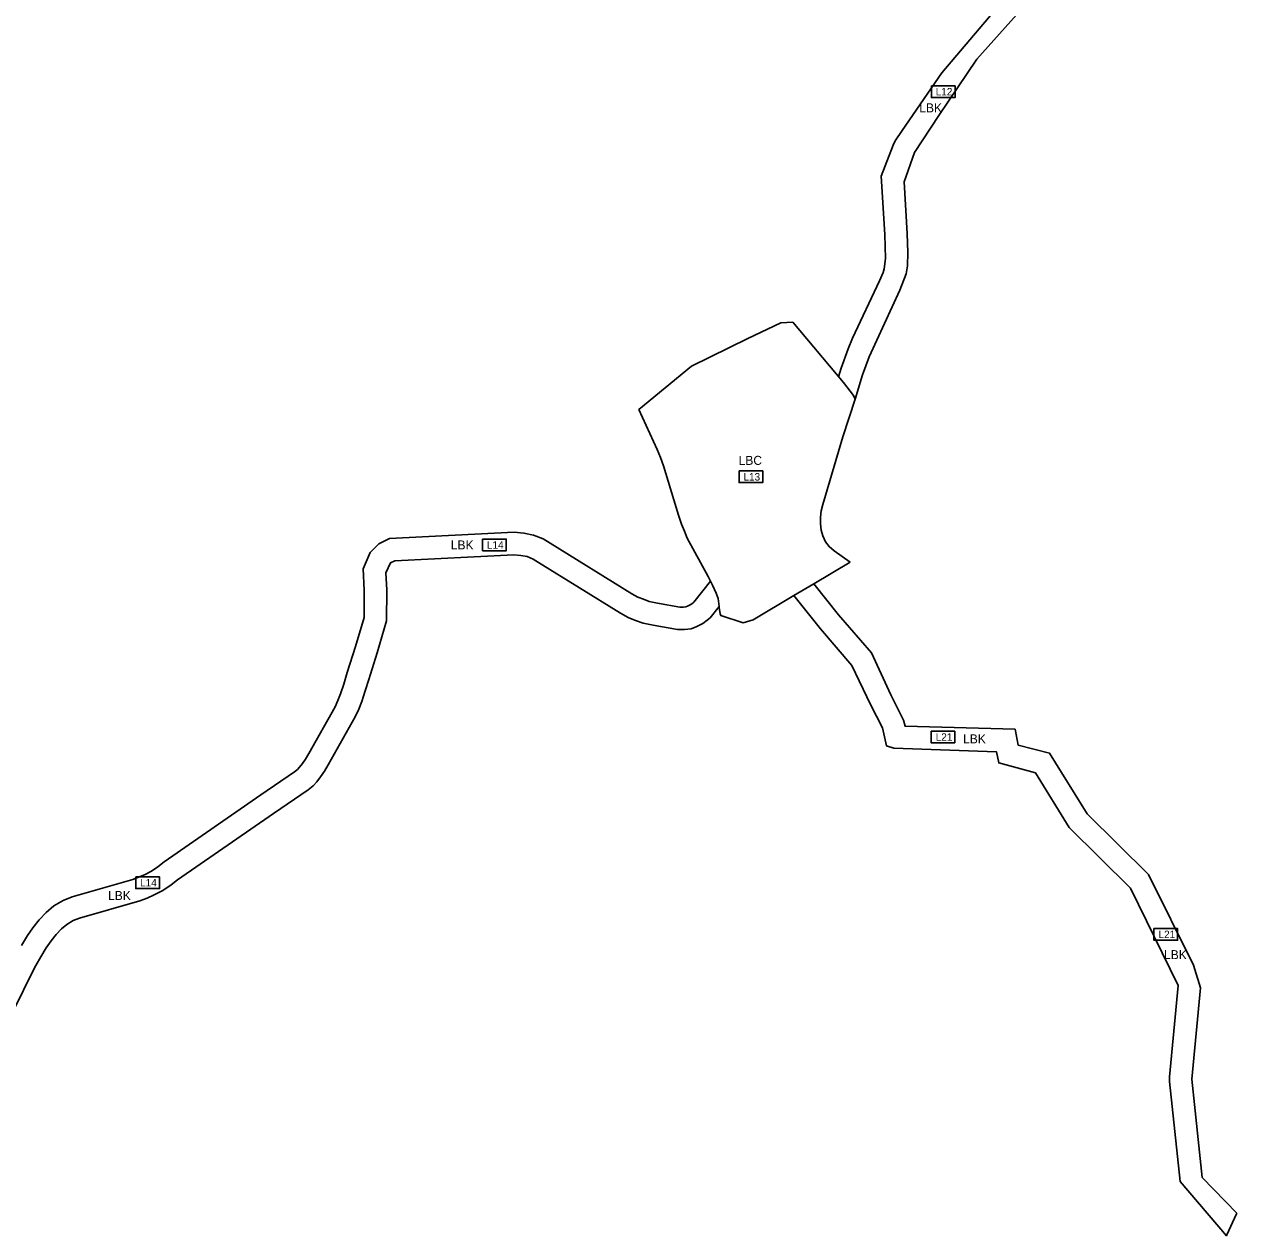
# Model space of a CAD drawing. Extents: x -546680 to -530218, y -1046521 to -1035695.
# Drawn here: x -543557 to -541938, y -1044212 to -1042594 of the extents above; entities that cross this region are included whole.
import ezdxf

# ---------------------------------------------------------------- set-up
doc = ezdxf.new("R2010")
doc.units = 0
for name, color, linetype in [('Vrstva 3', 7, 'Continuous'), ('Vrstva 32', 7, 'Continuous'), ('Vrstva 33', 7, 'Continuous'), ('Vrstva 54', 7, 'Continuous')]:
    doc.layers.add(name, color=color, linetype=linetype)

msp = doc.modelspace()

# ---------------------------------------------------------------- linework, layer by layer
at = {"layer": 'Vrstva 32'}
msp.add_lwpolyline([(-542454.2, -1043312.7), (-542475.8, -1043297.8), (-542482.5, -1043291.9), (-542487.1, -1043285.5), (-542490.8, -1043277.7), (-542492.9, -1043269.9), (-542493.8, -1043261.4), (-542493.8, -1043252.8), (-542492.8, -1043244.2), (-542491, -1043235.8), (-542463.9, -1043145.2), (-542447.7, -1043094.9), (-542450, -1043090), (-542463, -1043073), (-542531, -1042992), (-542547, -1042993), (-542591, -1043014), (-542666, -1043051), (-542736.3, -1043108.9), (-542711.9, -1043162.3), (-542707.4, -1043173.1), (-542703.5, -1043184), (-542683.7, -1043249.8), (-542679.3, -1043262), (-542675.7, -1043271.4), (-542671.8, -1043280.5), (-542644, -1043331.9), (-542638.1, -1043343.6), (-542633.4, -1043354), (-542630.6, -1043361.4), (-542629.4, -1043372.1), (-542629.2, -1043373.3), (-542628, -1043382), (-542627, -1043384), (-542597, -1043394), (-542584, -1043390), (-542529.4, -1043357.5), (-542502.8, -1043341.7), (-542454.2, -1043312.7)], dxfattribs=at)
at = {"layer": 'Vrstva 33'}
for points in [[(-542217, -1042565), (-542285, -1042641), (-542336, -1042716), (-542368.2, -1042765.8), (-542382, -1042805), (-542378.2, -1042873.7), (-542377.1, -1042899.3), (-542377.7, -1042916.8), (-542379.4, -1042927.8), (-542388, -1042949.6), (-542429.1, -1043038.7), (-542437.8, -1043062.7), (-542447.7, -1043094.9), (-542450, -1043090), (-542463, -1043073), (-542469.7, -1043065.1), (-542466.4, -1043053.6), (-542457.1, -1043027.7)], [(-542457.1, -1043027.7), (-542451.3, -1043013.8), (-542415.3, -1042937.2), (-542410.3, -1042925.9), (-542408.7, -1042920.9), (-542407.1, -1042907.3), (-542408.2, -1042875.2), (-542412.7, -1042797.4), (-542397, -1042756), (-542394, -1042750), (-542385, -1042736), (-542332, -1042659), (-542257, -1042571)], [(-543560.8, -1043824.8), (-543552.8, -1043811.6), (-543545.4, -1043801), (-543537.3, -1043790.3), (-543527.8, -1043780.5), (-543517.5, -1043772), (-543504.9, -1043764.7), (-543493.2, -1043759.9), (-543412, -1043736.5), (-543404.3, -1043733.6), (-543396.6, -1043730.2), (-543387.3, -1043725.4), (-543378.7, -1043719.6), (-543370.2, -1043712.8), (-543241.3, -1043623.7), (-543196, -1043592.7), (-543192.1, -1043589.5), (-543189.5, -1043586.7), (-543185.5, -1043581.5), (-543181.5, -1043575.9), (-543177.1, -1043568.4), (-543142, -1043505.9), (-543138.2, -1043497.6), (-543134.8, -1043488.6), (-543130.5, -1043475.6), (-543125.7, -1043460.3), (-543114.7, -1043425.3), (-543103.4, -1043386.6), (-543103, -1043350.2), (-543104.5, -1043321.7), (-543095, -1043299.9), (-543083.7, -1043288.4), (-543069.4, -1043281.1), (-542902.9, -1043272.8), (-542889.8, -1043274), (-542876.9, -1043276.6), (-542864, -1043281.8), (-542854.7, -1043287.5), (-542745.6, -1043355.1), (-542737.9, -1043359.4), (-542730.3, -1043362.4), (-542722.7, -1043365.1), (-542711.7, -1043367.4), (-542681.7, -1043372.7), (-542676.7, -1043372.8), (-542673.9, -1043372.5), (-542671.6, -1043371.6), (-542666.9, -1043369.1), (-542663.9, -1043366.9), (-542663.2, -1043366.3), (-542640.8, -1043338.2), (-542638.1, -1043343.6)], [(-542638.1, -1043343.6), (-542633.4, -1043354), (-542630.6, -1043361.4), (-542629.4, -1043372.1), (-542641.2, -1043386.9), (-542645.1, -1043390.4), (-542651, -1043394.6), (-542659, -1043398.9), (-542666.7, -1043401.9), (-542675.4, -1043402.8), (-542684.7, -1043402.7), (-542717.3, -1043396.8), (-542730.8, -1043394.1), (-542740.8, -1043390.5), (-542750.7, -1043386.6), (-542760.8, -1043381), (-542870.5, -1043313), (-542877.6, -1043308.6), (-542885.5, -1043305.4), (-542894.1, -1043303.7), (-542903.5, -1043302.9), (-543062.1, -1043310.8), (-543068.2, -1043313.6), (-543074.2, -1043327.2), (-543073, -1043349.6), (-543073.5, -1043391.1), (-543086, -1043434), (-543097.1, -1043469.3), (-543101.9, -1043484.8), (-543106.5, -1043498.7), (-543110.5, -1043509.2), (-543115.3, -1043519.5), (-543151.1, -1043583.4), (-543156.3, -1043592.1), (-543161.4, -1043599.5), (-543166.5, -1043606), (-543171.4, -1043611.4), (-543178.1, -1043616.8), (-543224.3, -1043648.5), (-543352.3, -1043737), (-543361, -1043743.8), (-543371.9, -1043751.1), (-543383.5, -1043757.3), (-543393.1, -1043761.4), (-543402.6, -1043765), (-543483.3, -1043788.3), (-543491.6, -1043791.6), (-543500.2, -1043796.7), (-543507.4, -1043802.6), (-543514.5, -1043809.9), (-543521.1, -1043818.6), (-543527.7, -1043828), (-543535, -1043840.1), (-543541.5, -1043851.4), (-543547.4, -1043862.6), (-543602.3, -1043973.4)], [(-542529.4, -1043357.5), (-542502.8, -1043341.7), (-542470, -1043383), (-542426, -1043434), (-542400, -1043490), (-542383, -1043524), (-542381, -1043532), (-542234, -1043536), (-542230, -1043557), (-542188, -1043568), (-542138, -1043649), (-542056, -1043730), (-541996, -1043851), (-541986.5, -1043881.2), (-541998, -1044003.2), (-541984.1, -1044134.5), (-541938.1, -1044182.4), (-541938.4, -1044183.3), (-541951.2, -1044211.3), (-541951.8, -1044212.5), (-542013.7, -1044140.2), (-542027.8, -1044006.4), (-542027.9, -1044000.4), (-542016.4, -1043878.4), (-542080, -1043748), (-542162, -1043667), (-542207, -1043594), (-542256, -1043581), (-542259, -1043566), (-542396, -1043561), (-542406, -1043558), (-542411, -1043534), (-542427, -1043503), (-542452, -1043451), (-542494, -1043402), (-542529.4, -1043357.5)]]:
    msp.add_lwpolyline(points, dxfattribs=at)
at = {"layer": 'Vrstva 54'}
for points in [[(-542345.9, -1042676.7), (-542345.9, -1042692.2), (-542314.2, -1042692.2), (-542314.2, -1042676.7), (-542345.9, -1042676.7)], [(-542602.7, -1043191), (-542602.7, -1043206.5), (-542571, -1043206.5), (-542571, -1043191), (-542602.7, -1043191)], [(-542945.1, -1043282), (-542945.1, -1043297.6), (-542913.4, -1043297.6), (-542913.4, -1043282), (-542945.1, -1043282)], [(-542346.3, -1043538.5), (-542346.3, -1043554), (-542314.6, -1043554), (-542314.6, -1043538.5), (-542346.3, -1043538.5)], [(-543408.1, -1043733.1), (-543408.1, -1043748.7), (-543376.4, -1043748.7), (-543376.4, -1043733.1), (-543408.1, -1043733.1)], [(-542048.8, -1043802.1), (-542048.8, -1043817.7), (-542017.1, -1043817.7), (-542017.1, -1043802.1), (-542048.8, -1043802.1)]]:
    msp.add_lwpolyline(points, dxfattribs=at)

# ---------------------------------------------------------------- texts
at = {"layer": 'Vrstva 3'}
for s, p in [('LBK', (-542362, -1042712)), ('LBC', (-542603.2, -1043182.8)), ('LBK', (-542987.5, -1043295.8)), ('LBK', (-542303.5, -1043554.8)), ('LBK', (-543445.1, -1043764)), ('LBK', (-542035.2, -1043843))]:
    msp.add_text(s, height=12, dxfattribs=at).set_placement(p)
at = {"layer": 'Vrstva 54'}
for s, p in [('L12', (-542340.1, -1042689.4)), ('L13', (-542596.8, -1043203.8)), ('L14', (-542939.3, -1043294.8)), ('L21', (-542340.1, -1043551.3)), ('L14', (-543402.4, -1043745.9)), ('L21', (-542042.6, -1043814.9))]:
    msp.add_text(s, height=10, dxfattribs=at).set_placement(p)

doc.saveas('drawing.dxf')
